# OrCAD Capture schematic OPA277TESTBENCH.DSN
size A
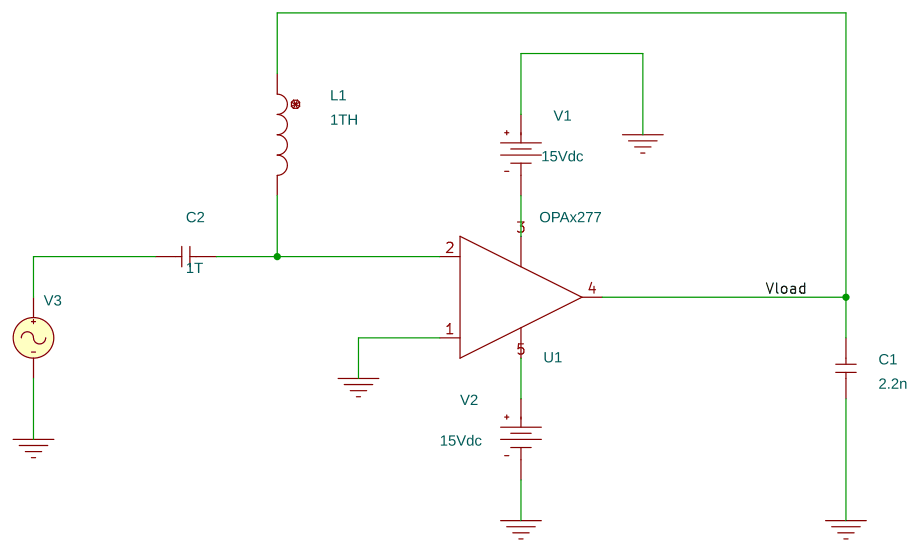
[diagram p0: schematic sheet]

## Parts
C1  2.2n  [cap196]
C2  1T  [cap196]
L1  1TH  [DISC350x175LS200x100034]
U1  OPAx277
V1  VDC
V2  VDC
V3  VAC

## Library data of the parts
C1 C2 = C
L1 = L
U1 = OPAx277
V1 V2 = VDC: DC: 15Vdc
V3 = VAC

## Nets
0: C1.1 U1.1(+) V1.0(+) V2.1(-) V3.2(-)
Vload: C1.2 L1.1 U1.4(OUT)
N00405: U1.5(V+) V2.0(+)
N00409: U1.3(V-) V1.1(-)
N00538: C2.1 V3.1(+)
N00545: C2.2 L1.2 U1.2(-)
